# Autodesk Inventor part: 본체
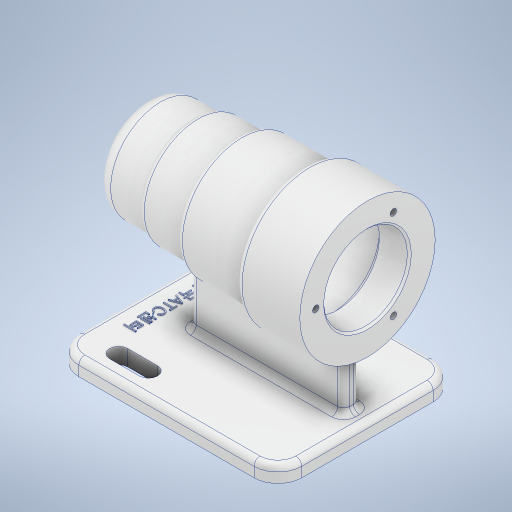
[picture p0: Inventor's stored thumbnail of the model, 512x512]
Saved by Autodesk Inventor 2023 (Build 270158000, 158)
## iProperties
Created: 2022-07
Part Number: 본체
Material: 알루미늄 6061
Document SubType Name: Modeling
Designer: owner
Density: 2.7 g/cm^3
Appearance: 알루미늄 - 평지
Mass: 663.189 g
Surface Area: 695.07 cm^2
Volume: 245.626 cm^3
Author: owner
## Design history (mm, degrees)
sketch "스케치1"
  geometry: L1 (-56, 70)-(56, 70); L2 (-56, 70)-(-56, 95); L3 (-56, 95)-(-32, 95); L4 (-32, 95)-(-32, 97); L5 (-32, 97)-(-10, 97); L6 (-10, 97)-(-10, 100); L7 (-10, 100)-(24, 100); L8 (24, 100)-(24, 104); L9 (24, 104)-(56, 104); L10 (56, 104)-(56, 70); 2 further points
  constraints: 20 end point, 6 perpendicular, 3 vertical, 1 horizontal, 1 midpoint, 1 vertical alignment
  dimensions: "d0" = 24 distance between parallel lines of L4 L2; "d1" = 46 distance between parallel lines of L6 L2; "d2" = 80 distance between parallel lines of L8 L2; "d3" = 112 distance between parallel lines of L10 L2; "d4" = 68 diameter of L9 L1; "d5" = 60 diameter of L7 L1; "d6" = 54 diameter of L5 L1; "d7" = 50 diameter of L3 L1; "d8" = 70 distance from line of point (0, 0) L1
revolve "회전1" sketch "스케치1" stored, may be unused: angle "d9" = 90 deg
sketch "스케치2"
  geometry: L1 (-56, 45)-(-56, 95) reference; L2 (56, 36)-(56, 104) reference; L3 (-56, 70)-(56, 70); L4 (-50, 70)-(-50, 77.5); L5 (-47, 80.5)-(-47, 80.5); L6 (-47, 80.5)-(-47, 85.7); L7 (-46.7, 86)-(-43, 86); L8 (-43, 86)-(-43, 87.2); L9 (-42.7, 87.5)-(-25, 87.5); L10 (-25, 87.5)-(-25, 90.7); L11 (-24.7, 91)-(-13, 91); L12 (-13, 91)-(-13, 91); L13 (-10, 94)-(38, 94); L14 (41, 91)-(41, 91); L15 (41, 91)-(56, 91); A1 r 0.3 centre (-46.7, 85.7) between (-46.7, 86) and (-47, 85.7); A2 r 0.3 centre (-42.7, 87.2) between (-42.7, 87.5) and (-43, 87.2); A3 r 0.3 centre (-24.7, 90.7) between (-24.7, 91) and (-25, 90.7); A4 r 3 centre (-47, 77.5) between (-47, 80.5) and (-50, 77.5); A5 r 3 centre (-10, 91) between (-10, 94) and (-13, 91); A6 r 3 centre (38, 91) between (41, 91) and (38, 94); 10 further points
  constraints: 26 end point, 14 point on line, 12 point on circle, 12 tangent, 9 perpendicular, 6 centre point, 4 equal radius, 2 midpoint, 2 vertical, 1 horizontal
  dimensions: "d10" = 15 distance between parallel lines of L14 L2; "d11" = 42 diameter of L15 L3; "d12" = 54 distance between parallel lines of L14 L12; "d13" = 48 diameter of L13 L3; "d14" = 12 distance between parallel lines of L12 L10; "d15" = 42 diameter of L11 L3; "d16" = 18 distance between parallel lines of L8 L10; "d17" = 35 diameter of L9 L3; "d18" = 32 diameter of L7 L3; "d19" = 4 distance between parallel lines of L8 L6; "d20" = 3 distance between parallel lines of L6 L4; "d21" = 21 diameter of L5 L3; "d23" = 0.3 radius of A1; "d24" = 3 radius of A4
revolve "회전2" sketch "스케치2" stored, may be unused: angle "d22" = 90 deg
sketch "스케치3"
  geometry: L1 (-56, 45)-(56, 45); L2 (56, 45)-(56, -45); L3 (56, -45)-(-56, -45); L4 (-56, -45)-(-56, 45); L5 (-56, 45)-(56, -45); L6 (56, 45)-(-56, -45); L7 (56, 0)-(-56, 0); L8 (56, -33)-(-56, -33); L9 (56, 33)-(-56, 33); L10 (36, 33)-(21, 33); L11 (36, 37.5)-(21, 37.5); L12 (21, 28.5)-(36, 28.5); L13 (0, 45)-(0, -45); L14 (21, -28.5)-(36, -28.5); L15 (36, -37.5)-(21, -37.5); L16 (-4, 33)-(-17.708, 33); L17 (-4, 37.5)-(-17.708, 37.5); L18 (-17.708, 28.5)-(-4, 28.5); L19 (-17.708, -28.5)-(-4, -28.5); L20 (-4, -37.5)-(-17.708, -37.5); A1 r 4.5 centre (36, 33) between (36, 28.5) and (36, 37.5); A2 r 4.5 centre (21, 33) between (21, 37.5) and (21, 28.5); A3 r 4.5 centre (21, -33) between (21, -28.5) and (21, -37.5); A4 r 4.5 centre (36, -33) between (36, -37.5) and (36, -28.5); A5 r 4.5 centre (-4, 33) between (-4, 28.5) and (-4, 37.5); A6 r 4.5 centre (-17.708, 33) between (-17.708, 37.5) and (-17.708, 28.5); A7 r 4.5 centre (-17.708, -33) between (-17.708, -28.5) and (-17.708, -37.5); A8 r 4.5 centre (-4, -33) between (-4, -37.5) and (-4, -28.5); 5 further points
  constraints: 44 end point, 18 point on circle, 12 symmetric about line, 8 centre point, 8 midpoint, 8 point on line, 8 tangent, 6 parallel, 3 perpendicular, 1 collinear, 1 horizontal, 1 horizontal alignment, 1 vertical alignment, 4 other
  dimensions: "d25" = 112 distance of L2.end L3.end; "d26" = 90 distance of L1.end L2.end; "d27" = 33 distance between parallel lines of L7 L8; "d28" = 33 distance between parallel lines of L7 L9; "d29" = 9 distance between parallel lines of L11 L12; "d30" = 20 distance from line of L11.start L2; "d31" = 15 distance of L11.end L11.start; "d69" = 25 distance of L17.start L11.end; "d71" = 9 distance between parallel lines of L18 L17
extrude "돌출1" join sketch "스케치3" distance "d32" = 8; taper "d33" = 0 deg
sketch "스케치4"
  geometry: L1 (-29, 4)-(48, 4); L2 (48, 4)-(48, -4); L3 (48, -4)-(-29, -4); L4 (-29, -4)-(-29, 4); L5 (56, -45)-(56, 45) reference; 2 further points
  constraints: 8 end point, 2 parallel, 1 horizontal, 1 horizontal alignment, 1 midpoint, 1 perpendicular
  dimensions: "d34" = 8 distance between parallel lines of L5 L2; "d35" = 77 distance between parallel lines of L4 L2; "d36" = 8 distance between parallel lines of L3 L1
extrude "돌출2" join sketch "스케치4" stored distance "d37" = 8; taper "d38" = 0 deg
sketch "스케치7" dims "d54" = 52
  geometry: C1 r 16 at (0, 0) reference; 3 further points
  constraints: 2 horizontal alignment, 1 coincident, 2 other
hole "구멍1" sketch "스케치7" at (-26, 0) diameter "d47" = 3.242; stored, may be unused: countersink angle "d51" = 90 deg, drill point angle "d53" = 118 deg; dims "d48" = 8, "d49" = 4, "d50" = 2, "d52" = 11
fillet "모깎기1" dims "d58" = 12
fillet "모깎기2" dims "d59" = 3
chamfer "모따기1" distance "d60" = 1; stored, may be unused: second distance "d61" = 2, angle "d62" = 45 deg
fillet "모깎기3" dims "d63" = 3
sketch "스케치8"
  geometry: L1 (-56, 33)-(-56, -33) reference; 3 further points
  constraints: 1 horizontal alignment, 1 midpoint, 1 other
  dimensions: "d64" = 12 distance from line of point (-44, 0) L1
feature "엠보싱1" sketch "스케치8" dims "d0" = 24, "d1" = 46, "d2" = 80, "d3" = 112, "d4" = 68, "d5" = 60, "d6" = 54, "d7" = 50, "d8" = 70, "d65" = 0.5, "d66" = 0
fillet "모깎기5" dims "d68" = 3
fillet "모깎기6" dims "d72" = 8
node "솔리드1"
pattern_circular "원형 패턴1" dims angle "d56" = 360 deg
feature "A9D066F2-1C7D-4E18-AEED-F7BC21143FA4" dims "d47" = 3.242, "d48" = 8, "d49" = 4, "d50" = 2, "d51" = 90 deg, "d52" = 11, "d53" = 118 deg
